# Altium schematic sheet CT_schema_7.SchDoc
size 252 x 159 mm
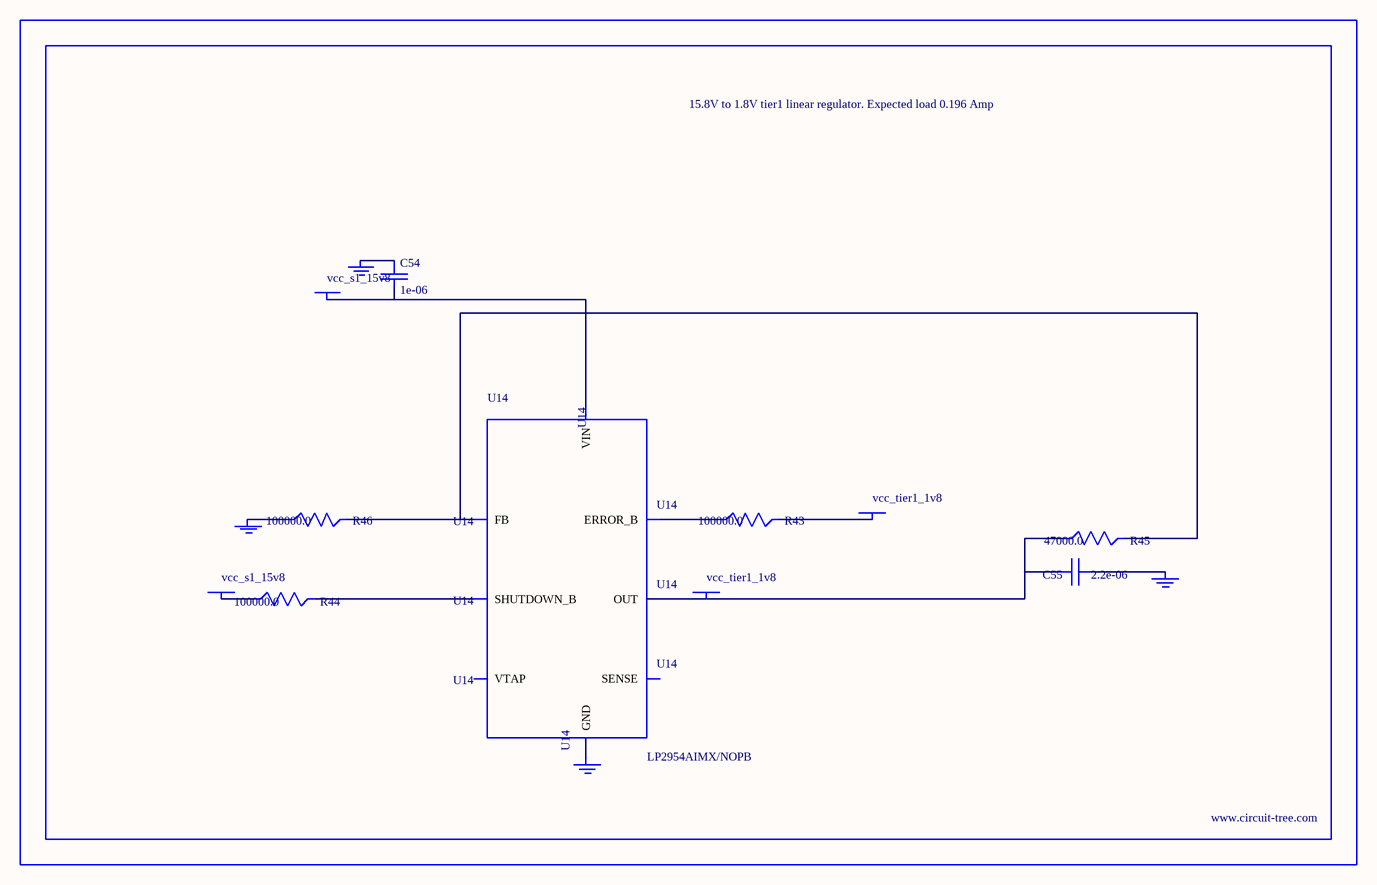
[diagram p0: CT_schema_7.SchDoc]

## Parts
BORDER6  (no value)
C54  1e-06  [EXV-9B]
C55  2.2e-06  [EXV-9B]
GND_INSTANCE_6_0  (no value)
GND_INSTANCE_6_1  (no value)
GND_INSTANCE_6_2  (no value)
GND_INSTANCE_6_3  (no value)
POWER_INSTANCE_6_0  vcc_s1_15v8
POWER_INSTANCE_6_1  vcc_tier1_1v8
POWER_INSTANCE_6_2  vcc_s1_15v8
POWER_INSTANCE_6_3  vcc_tier1_1v8
R43  100000.0  [R0603]
R44  100000.0  [R0603]
R45  47000.0  [R0603]
R46  100000.0  [R0603]
U14  LP2954AIMX/NOPB  [LP2954]

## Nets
NetC54_1: C54.1 GND_INSTANCE_6_2.0(GND)
NetC54_2: C54.2 POWER_INSTANCE_6_2.0(PWR) U14.8(VIN)
NetC55_1: C55.1 GND_INSTANCE_6_0.0(GND)
NetC55_2: C55.2 POWER_INSTANCE_6_3.0(PWR) R45.1 U14.1(OUT)
NetGND_INSTANCE_6_1_0: GND_INSTANCE_6_1.0(GND) R46.1
NetGND_INSTANCE_6_3_0: GND_INSTANCE_6_3.0(GND) U14.4(GND)
NetPOWER_INSTANCE_6_0_0: POWER_INSTANCE_6_0.0(PWR) R44.1
NetPOWER_INSTANCE_6_1_0: POWER_INSTANCE_6_1.0(PWR) R43.2
NetR43_1: R43.1 U14.5(ERROR_B)
NetR44_2: R44.2 U14.3(SHUTDOWN_B)
NetR45_2: R45.2 R46.2 U14.7(FB)

Not connected (* = marked no-connect by the designer): U14 2(SENSE) 6(VTAP)

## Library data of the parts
BORDER6 = BORDER_PAGE6
C54 = EDK105M050A9BAA
C55 = EDK225M050A9BAA
GND_INSTANCE_6_0-GND_INSTANCE_6_3 = GND
POWER_INSTANCE_6_0-POWER_INSTANCE_6_3 = PWR
R43 R44 R46 = RC0603JR-07100KL
R45 = RC0603JR-0747KL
